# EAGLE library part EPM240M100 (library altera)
EPM240M100 Low-cost, low-power CPLD Auto generated by make-symbol-device-package-bsdl.ulp Rev. 36 Source: EPM240M100.BSD
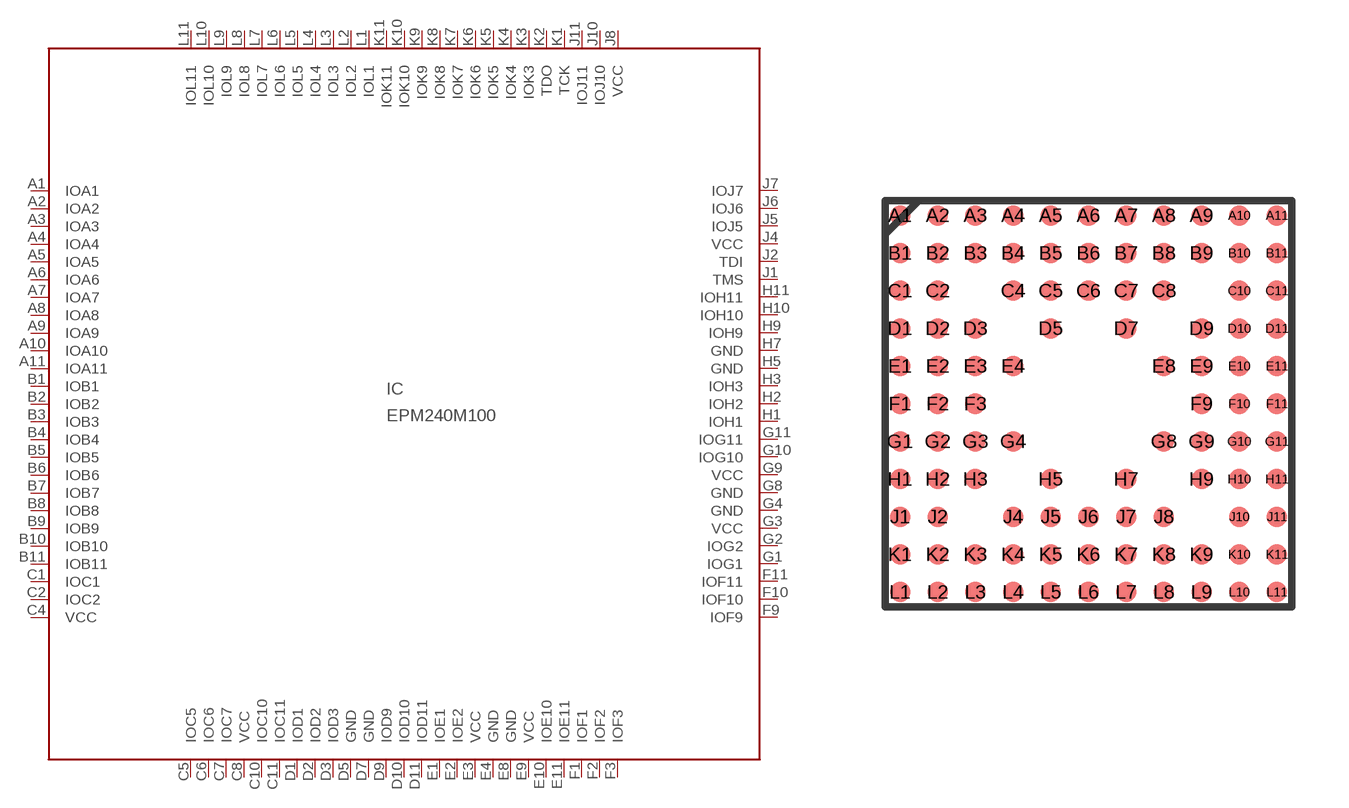
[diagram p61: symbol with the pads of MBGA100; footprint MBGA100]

Designator prefix IC

## EPM240M100 (MPN: EPM240M100C4N; OC_FARNELL: 1635095; OC_NEWARK: 51R0493)  [MBGA100]
A1  IOA1
A2  IOA2
A3  IOA3
A4  IOA4
A5  IOA5
A6  IOA6
A7  IOA7
A8  IOA8
A9  IOA9
A10  IOA10
A11  IOA11
B1  IOB1
B2  IOB2
B3  IOB3
B4  IOB4
B5  IOB5
B6  IOB6
B7  IOB7
B8  IOB8
B9  IOB9
B10  IOB10
B11  IOB11
C1  IOC1
C2  IOC2
C4  VCC  pwr
C5  IOC5
C6  IOC6
C7  IOC7
C8  VCC  pwr
C10  IOC10
C11  IOC11
D1  IOD1
D2  IOD2
D3  IOD3
D5  GND  pwr
D7  GND  pwr
D9  IOD9
D10  IOD10
D11  IOD11
E1  IOE1
E2  IOE2
E3  VCC  pwr
E4  GND  pwr
E8  GND  pwr
E9  VCC  pwr
E10  IOE10
E11  IOE11
F1  IOF1
F2  IOF2
F3  IOF3
F9  IOF9
F10  IOF10
F11  IOF11
G1  IOG1
G2  IOG2
G3  VCC  pwr
G4  GND  pwr
G8  GND  pwr
G9  VCC  pwr
G10  IOG10
G11  IOG11
H1  IOH1
H2  IOH2
H3  IOH3
H5  GND  pwr
H7  GND  pwr
H9  IOH9
H10  IOH10
H11  IOH11
J1  TMS  in
J2  TDI  in
J4  VCC  pwr
J5  IOJ5
J6  IOJ6
J7  IOJ7
J8  VCC  pwr
J10  IOJ10
J11  IOJ11
K1  TCK  in
K2  TDO  out
K3  IOK3
K4  IOK4
K5  IOK5
K6  IOK6
K7  IOK7
K8  IOK8
K9  IOK9
K10  IOK10
K11  IOK11
L1  IOL1
L2  IOL2
L3  IOL3
L4  IOL4
L5  IOL5
L6  IOL6
L7  IOL7
L8  IOL8
L9  IOL9
L10  IOL10
L11  IOL11

## Footprint MBGA100 (pad centres in mm)
EPM240M100 edit this description Auto generated by make-symbol-device-package-bsdl.ulp Rev. 36 Source: EPM240M100.BSD
smd 0.55 x 0.55: A1 -5,5; A2 -4,5; A3 -3,5; A4 -2,5; A5 -1,5; A6 0,5; A7 1,5; A8 2,5; A9 3,5; A10 4,5; A11 5,5; B1 -5,4; B2 -4,4; B3 -3,4; B4 -2,4; B5 -1,4; B6 0,4; B7 1,4; B8 2,4; B9 3,4; B10 4,4; B11 5,4; C1 -5,3; C2 -4,3; C4 -2,3; C5 -1,3; C6 0,3; C7 1,3; C8 2,3; C10 4,3; C11 5,3; D1 -5,2; D2 -4,2; D3 -3,2; D5 -1,2; D7 1,2; D9 3,2; D10 4,2; D11 5,2; E1 -5,1; E2 -4,1; E3 -3,1; E4 -2,1; E8 2,1; E9 3,1; E10 4,1; E11 5,1; F1 -5,0; F2 -4,0; F3 -3,0; F9 3,0; F10 4,0; F11 5,0; G1 -5,-1; G2 -4,-1; G3 -3,-1; G4 -2,-1; G8 2,-1; G9 3,-1; G10 4,-1; G11 5,-1; H1 -5,-2; H2 -4,-2; H3 -3,-2; H5 -1,-2; H7 1,-2; H9 3,-2; H10 4,-2; H11 5,-2; J1 -5,-3; J2 -4,-3; J4 -2,-3; J5 -1,-3; J6 0,-3; J7 1,-3; J8 2,-3; J10 4,-3; J11 5,-3; K1 -5,-4; K2 -4,-4; K3 -3,-4; K4 -2,-4; K5 -1,-4; K6 0,-4; K7 1,-4; K8 2,-4; K9 3,-4; K10 4,-4; K11 5,-4; L1 -5,-5; L2 -4,-5; L3 -3,-5; L4 -2,-5; L5 -1,-5; L6 0,-5; L7 1,-5; L8 2,-5; L9 3,-5; L10 4,-5; L11 5,-5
